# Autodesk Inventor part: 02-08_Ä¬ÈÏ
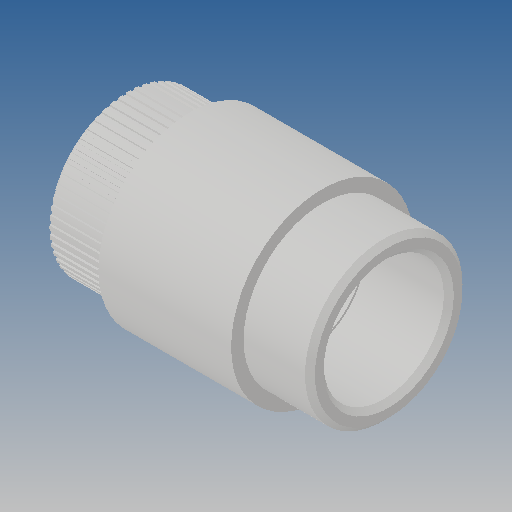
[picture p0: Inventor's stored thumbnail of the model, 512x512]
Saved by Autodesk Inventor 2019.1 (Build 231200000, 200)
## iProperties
Created: 2010-06
Part Number: 02-08_Ä¬ÈÏ
Material: Ogólny
Document SubType Name: Modeling
Designer: CADENGINEERING4
Density: 1 g/cm^3
Appearance: Domyślna
Author: CADENGINEERING4
Revision Number: ÈÎºÎ
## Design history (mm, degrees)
feature "NONE"
node "Bryła1"
